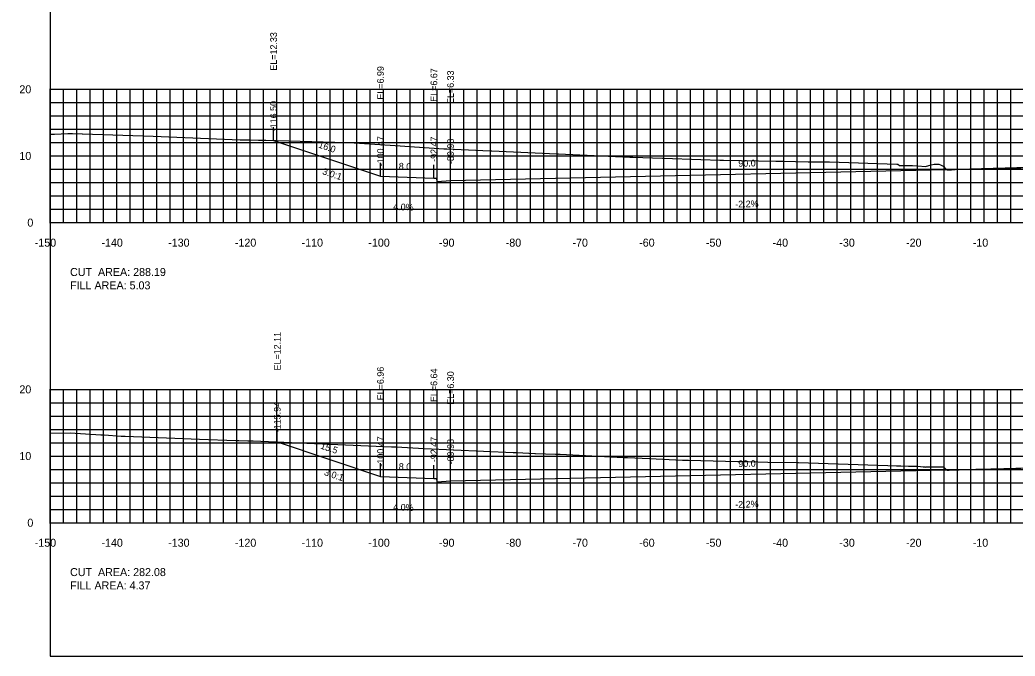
# Model space of a CAD drawing. Extents: x 1797419 to 1809236, y 248759 to 251512.
# Drawn here: x 1805196.5 to 1805345.6, y 250854.9 to 250950.3 of the extents above; entities that cross this region are included whole.
import ezdxf

# ---------------------------------------------------------------- set-up
doc = ezdxf.new("R2010")
doc.units = 0
for name, color, linetype in [('10', 7, 'Continuous'), ('3', 7, 'Continuous'), ('31', 7, 'Continuous'), ('4', 7, 'Continuous'), ('60', 7, 'Continuous'), ('ANNO-TXT', 7, 'Continuous'), ('CL-CNST', 7, 'Continuous'), ('Level 62', 7, 'Continuous'), ('M-ROADS', 7, 'Continuous')]:
    doc.layers.add(name, color=color, linetype=linetype)

msp = doc.modelspace()

# ---------------------------------------------------------------- linework, layer by layer
for p, q in [((1805234.5, 250932.22), (1805234.5, 250934.22)), ((1805250.53, 250926.88), (1805250.53, 250928.88)), ((1805258.53, 250926.56), (1805258.53, 250928.56)), ((1805261.03, 250926.22), (1805261.03, 250928.22)), ((1805235.06, 250887), (1805235.06, 250889)), ((1805250.53, 250881.84), (1805250.53, 250883.84)), ((1805258.53, 250881.52), (1805258.53, 250883.52)), ((1805261.03, 250881.19), (1805261.03, 250883.19))]:
    msp.add_line(p, q)
msp.add_lwpolyline([(1805201, 250854.89), (1805501, 250854.89), (1805501, 251044.89), (1805201, 251044.89)], close=True)
at = {"layer": '60'}
for p, q in [((1805200.94, 250939.89), (1805201, 250939.89)), ((1805201, 250919.89), (1805201, 250939.89)), ((1805200.94, 250929.89), (1805201, 250929.89)), ((1805200.94, 250919.89), (1805201, 250919.89)), ((1805201, 250919.89), (1805501, 250919.89)), ((1805201, 250919.83), (1805201, 250919.89)), ((1805211, 250919.83), (1805211, 250919.89)), ((1805221, 250919.83), (1805221, 250919.89)), ((1805231, 250919.83), (1805231, 250919.89)), ((1805241, 250919.83), (1805241, 250919.89)), ((1805251, 250919.83), (1805251, 250919.89)), ((1805261, 250919.83), (1805261, 250919.89)), ((1805271, 250919.83), (1805271, 250919.89)), ((1805281, 250919.83), (1805281, 250919.89)), ((1805291, 250919.83), (1805291, 250919.89)), ((1805301, 250919.83), (1805301, 250919.89)), ((1805311, 250919.83), (1805311, 250919.89)), ((1805321, 250919.83), (1805321, 250919.89)), ((1805331, 250919.83), (1805331, 250919.89)), ((1805341, 250919.83), (1805341, 250919.89)), ((1805200.94, 250894.89), (1805201, 250894.89)), ((1805201, 250874.89), (1805201, 250894.89)), ((1805200.94, 250884.89), (1805201, 250884.89)), ((1805200.94, 250874.89), (1805201, 250874.89)), ((1805201, 250874.89), (1805501, 250874.89)), ((1805201, 250874.83), (1805201, 250874.89)), ((1805211, 250874.83), (1805211, 250874.89)), ((1805221, 250874.83), (1805221, 250874.89)), ((1805231, 250874.83), (1805231, 250874.89)), ((1805241, 250874.83), (1805241, 250874.89)), ((1805251, 250874.83), (1805251, 250874.89)), ((1805261, 250874.83), (1805261, 250874.89)), ((1805271, 250874.83), (1805271, 250874.89)), ((1805281, 250874.83), (1805281, 250874.89)), ((1805291, 250874.83), (1805291, 250874.89)), ((1805301, 250874.83), (1805301, 250874.89)), ((1805311, 250874.83), (1805311, 250874.89)), ((1805321, 250874.83), (1805321, 250874.89)), ((1805331, 250874.83), (1805331, 250874.89)), ((1805341, 250874.83), (1805341, 250874.89))]:
    msp.add_line(p, q, dxfattribs=at)
at = {"layer": 'CL-CNST'}
for points in [[(1805234.5, 250932.22), (1805250.53, 250926.88), (1805258.53, 250926.56), (1805258.86, 250926.56), (1805259.03, 250926.06), (1805261.03, 250926.22), (1805351, 250928.2), (1805412.92, 250928.2), (1805414.92, 250928.04), (1805415.08, 250928.54), (1805415.41, 250928.54), (1805417.41, 250928.62), (1805422.41, 250928.72), (1805423.41, 250928.76), (1805425.93, 250927.92)], [(1805235.06, 250887), (1805250.53, 250881.84), (1805258.53, 250881.52), (1805258.86, 250881.52), (1805259.03, 250881.02), (1805261.03, 250881.19), (1805351, 250883.17), (1805414.66, 250882.89), (1805416.66, 250882.72), (1805416.82, 250883.22), (1805417.15, 250883.22), (1805419.15, 250883.3), (1805424.15, 250883.4), (1805425.15, 250883.44), (1805426.89, 250882.86)]]:
    msp.add_lwpolyline(points, dxfattribs=at)
at = {"layer": 'Level 62'}
for p, q in [((1805201, 250939.89), (1805501, 250939.89)), ((1805201, 250919.89), (1805201, 250939.89)), ((1805203, 250919.89), (1805203, 250939.89)), ((1805205, 250919.89), (1805205, 250939.89)), ((1805207, 250919.89), (1805207, 250939.89)), ((1805209, 250919.89), (1805209, 250939.89)), ((1805211, 250919.89), (1805211, 250939.89)), ((1805213, 250919.89), (1805213, 250939.89)), ((1805215, 250919.89), (1805215, 250939.89)), ((1805217, 250919.89), (1805217, 250939.89)), ((1805219, 250919.89), (1805219, 250939.89)), ((1805221, 250919.89), (1805221, 250939.89)), ((1805223, 250919.89), (1805223, 250939.89)), ((1805225, 250919.89), (1805225, 250939.89)), ((1805227, 250919.89), (1805227, 250939.89)), ((1805229, 250919.89), (1805229, 250939.89)), ((1805231, 250919.89), (1805231, 250939.89)), ((1805233, 250919.89), (1805233, 250939.89)), ((1805235, 250919.89), (1805235, 250939.89)), ((1805237, 250919.89), (1805237, 250939.89)), ((1805239, 250919.89), (1805239, 250939.89)), ((1805241, 250919.89), (1805241, 250939.89)), ((1805243, 250919.89), (1805243, 250939.89)), ((1805245, 250919.89), (1805245, 250939.89)), ((1805247, 250919.89), (1805247, 250939.89)), ((1805249, 250919.89), (1805249, 250939.89)), ((1805251, 250919.89), (1805251, 250939.89)), ((1805253, 250919.89), (1805253, 250939.89)), ((1805255, 250919.89), (1805255, 250939.89)), ((1805257, 250919.89), (1805257, 250939.89)), ((1805259, 250919.89), (1805259, 250939.89)), ((1805261, 250919.89), (1805261, 250939.89)), ((1805263, 250919.89), (1805263, 250939.89)), ((1805265, 250919.89), (1805265, 250939.89)), ((1805267, 250919.89), (1805267, 250939.89)), ((1805269, 250919.89), (1805269, 250939.89)), ((1805271, 250919.89), (1805271, 250939.89)), ((1805273, 250919.89), (1805273, 250939.89)), ((1805275, 250919.89), (1805275, 250939.89)), ((1805277, 250919.89), (1805277, 250939.89)), ((1805279, 250919.89), (1805279, 250939.89)), ((1805281, 250919.89), (1805281, 250939.89)), ((1805283, 250919.89), (1805283, 250939.89)), ((1805285, 250919.89), (1805285, 250939.89)), ((1805287, 250919.89), (1805287, 250939.89)), ((1805289, 250919.89), (1805289, 250939.89)), ((1805291, 250919.89), (1805291, 250939.89)), ((1805293, 250919.89), (1805293, 250939.89)), ((1805295, 250919.89), (1805295, 250939.89)), ((1805297, 250919.89), (1805297, 250939.89)), ((1805299, 250919.89), (1805299, 250939.89)), ((1805301, 250919.89), (1805301, 250939.89)), ((1805303, 250919.89), (1805303, 250939.89)), ((1805305, 250919.89), (1805305, 250939.89)), ((1805307, 250919.89), (1805307, 250939.89)), ((1805309, 250919.89), (1805309, 250939.89)), ((1805311, 250919.89), (1805311, 250939.89)), ((1805313, 250919.89), (1805313, 250939.89)), ((1805315, 250919.89), (1805315, 250939.89)), ((1805317, 250919.89), (1805317, 250939.89)), ((1805319, 250919.89), (1805319, 250939.89)), ((1805321, 250919.89), (1805321, 250939.89)), ((1805323, 250919.89), (1805323, 250939.89)), ((1805325, 250919.89), (1805325, 250939.89)), ((1805327, 250919.89), (1805327, 250939.89)), ((1805329, 250919.89), (1805329, 250939.89)), ((1805331, 250919.89), (1805331, 250939.89)), ((1805333, 250919.89), (1805333, 250939.89)), ((1805335, 250919.89), (1805335, 250939.89)), ((1805337, 250919.89), (1805337, 250939.89)), ((1805339, 250919.89), (1805339, 250939.89)), ((1805341, 250919.89), (1805341, 250939.89)), ((1805343, 250919.89), (1805343, 250939.89)), ((1805345, 250919.89), (1805345, 250939.89)), ((1805201, 250937.89), (1805501, 250937.89)), ((1805201, 250935.89), (1805501, 250935.89)), ((1805201, 250933.89), (1805501, 250933.89)), ((1805201, 250931.89), (1805501, 250931.89)), ((1805201, 250929.89), (1805501, 250929.89)), ((1805201, 250927.89), (1805501, 250927.89)), ((1805201, 250925.89), (1805501, 250925.89)), ((1805201, 250923.89), (1805501, 250923.89)), ((1805201, 250921.89), (1805501, 250921.89)), ((1805201, 250919.89), (1805501, 250919.89)), ((1805201, 250894.89), (1805501, 250894.89)), ((1805201, 250874.89), (1805201, 250894.89)), ((1805203, 250874.89), (1805203, 250894.89)), ((1805205, 250874.89), (1805205, 250894.89)), ((1805207, 250874.89), (1805207, 250894.89)), ((1805209, 250874.89), (1805209, 250894.89)), ((1805211, 250874.89), (1805211, 250894.89)), ((1805213, 250874.89), (1805213, 250894.89)), ((1805215, 250874.89), (1805215, 250894.89)), ((1805217, 250874.89), (1805217, 250894.89)), ((1805219, 250874.89), (1805219, 250894.89)), ((1805221, 250874.89), (1805221, 250894.89)), ((1805223, 250874.89), (1805223, 250894.89)), ((1805225, 250874.89), (1805225, 250894.89)), ((1805227, 250874.89), (1805227, 250894.89)), ((1805229, 250874.89), (1805229, 250894.89)), ((1805231, 250874.89), (1805231, 250894.89)), ((1805233, 250874.89), (1805233, 250894.89)), ((1805235, 250874.89), (1805235, 250894.89)), ((1805237, 250874.89), (1805237, 250894.89)), ((1805239, 250874.89), (1805239, 250894.89)), ((1805241, 250874.89), (1805241, 250894.89)), ((1805243, 250874.89), (1805243, 250894.89)), ((1805245, 250874.89), (1805245, 250894.89)), ((1805247, 250874.89), (1805247, 250894.89)), ((1805249, 250874.89), (1805249, 250894.89)), ((1805251, 250874.89), (1805251, 250894.89)), ((1805253, 250874.89), (1805253, 250894.89)), ((1805255, 250874.89), (1805255, 250894.89)), ((1805257, 250874.89), (1805257, 250894.89)), ((1805259, 250874.89), (1805259, 250894.89)), ((1805261, 250874.89), (1805261, 250894.89)), ((1805263, 250874.89), (1805263, 250894.89)), ((1805265, 250874.89), (1805265, 250894.89)), ((1805267, 250874.89), (1805267, 250894.89)), ((1805269, 250874.89), (1805269, 250894.89)), ((1805271, 250874.89), (1805271, 250894.89)), ((1805273, 250874.89), (1805273, 250894.89)), ((1805275, 250874.89), (1805275, 250894.89)), ((1805277, 250874.89), (1805277, 250894.89)), ((1805279, 250874.89), (1805279, 250894.89)), ((1805281, 250874.89), (1805281, 250894.89)), ((1805283, 250874.89), (1805283, 250894.89)), ((1805285, 250874.89), (1805285, 250894.89)), ((1805287, 250874.89), (1805287, 250894.89)), ((1805289, 250874.89), (1805289, 250894.89)), ((1805291, 250874.89), (1805291, 250894.89)), ((1805293, 250874.89), (1805293, 250894.89)), ((1805295, 250874.89), (1805295, 250894.89)), ((1805297, 250874.89), (1805297, 250894.89)), ((1805299, 250874.89), (1805299, 250894.89)), ((1805301, 250874.89), (1805301, 250894.89)), ((1805303, 250874.89), (1805303, 250894.89)), ((1805305, 250874.89), (1805305, 250894.89)), ((1805307, 250874.89), (1805307, 250894.89)), ((1805309, 250874.89), (1805309, 250894.89)), ((1805311, 250874.89), (1805311, 250894.89)), ((1805313, 250874.89), (1805313, 250894.89)), ((1805315, 250874.89), (1805315, 250894.89)), ((1805317, 250874.89), (1805317, 250894.89)), ((1805319, 250874.89), (1805319, 250894.89)), ((1805321, 250874.89), (1805321, 250894.89)), ((1805323, 250874.89), (1805323, 250894.89)), ((1805325, 250874.89), (1805325, 250894.89)), ((1805327, 250874.89), (1805327, 250894.89)), ((1805329, 250874.89), (1805329, 250894.89)), ((1805331, 250874.89), (1805331, 250894.89)), ((1805333, 250874.89), (1805333, 250894.89)), ((1805335, 250874.89), (1805335, 250894.89)), ((1805337, 250874.89), (1805337, 250894.89)), ((1805339, 250874.89), (1805339, 250894.89)), ((1805341, 250874.89), (1805341, 250894.89)), ((1805343, 250874.89), (1805343, 250894.89)), ((1805345, 250874.89), (1805345, 250894.89)), ((1805201, 250892.89), (1805501, 250892.89)), ((1805201, 250890.89), (1805501, 250890.89)), ((1805201, 250888.89), (1805501, 250888.89)), ((1805201, 250886.89), (1805501, 250886.89)), ((1805201, 250884.89), (1805501, 250884.89)), ((1805201, 250882.89), (1805501, 250882.89)), ((1805201, 250880.89), (1805501, 250880.89)), ((1805201, 250878.89), (1805501, 250878.89)), ((1805201, 250876.89), (1805501, 250876.89)), ((1805201, 250874.89), (1805501, 250874.89))]:
    msp.add_line(p, q, dxfattribs=at)
at = {"layer": 'M-ROADS'}
for points in [[(1805201, 250933.16), (1805201.69, 250933.18), (1805203.64, 250933.26), (1805203.67, 250933.26), (1805204.01, 250933.26), (1805204.04, 250933.26), (1805204.35, 250933.26), (1805205.81, 250933.2), (1805205.87, 250933.2), (1805216.45, 250932.87), (1805229.48, 250932.33), (1805230.03, 250932.32), (1805230.07, 250932.32), (1805230.96, 250932.29), (1805232.25, 250932.27), (1805233.17, 250932.25), (1805233.35, 250932.25), (1805245.4, 250931.91), (1805245.59, 250931.91), (1805245.83, 250931.9), (1805252.71, 250931.48), (1805260, 250930.98), (1805260.3, 250930.97), (1805260.45, 250930.97), (1805266.99, 250930.65), (1805267.2, 250930.64), (1805276.96, 250930.21), (1805277.21, 250930.21), (1805287.9, 250929.71), (1805288.37, 250929.7), (1805292.78, 250929.56), (1805292.9, 250929.56), (1805298.56, 250929.38), (1805301.39, 250929.28), (1805301.75, 250929.28), (1805301.93, 250929.28), (1805309.77, 250929.12), (1805310.23, 250929.11), (1805310.83, 250929.1), (1805314.62, 250929.01), (1805314.69, 250929.01), (1805317.18, 250929), (1805317.28, 250929), (1805317.82, 250929.01), (1805327.9, 250928.68), (1805327.91, 250928.68), (1805328.05, 250928.68), (1805328.32, 250928.44), (1805328.47, 250928.45), (1805328.97, 250928.45), (1805329.17, 250928.45), (1805329.32, 250928.45), (1805329.54, 250928.45), (1805329.67, 250928.45), (1805330.29, 250928.44), (1805331.07, 250928.42), (1805332.22, 250928.32), (1805333.06, 250928.57), (1805333.49, 250928.66), (1805333.51, 250928.66), (1805333.86, 250928.66), (1805333.88, 250928.66), (1805334.19, 250928.66), (1805334.2, 250928.66), (1805334.2, 250928.66), (1805334.48, 250928.55), (1805334.95, 250928.32), (1805335.08, 250928.15), (1805335.41, 250927.81), (1805336.1, 250927.83), (1805336.14, 250927.84), (1805336.18, 250927.85), (1805336.18, 250927.85), (1805336.22, 250927.85), (1805336.27, 250927.85), (1805336.3, 250927.85), (1805336.32, 250927.85), (1805336.37, 250927.85), (1805336.44, 250927.84), (1805336.45, 250927.84), (1805336.51, 250927.85), (1805336.58, 250927.87), (1805336.64, 250927.88), (1805336.67, 250927.88), (1805336.77, 250927.9), (1805336.88, 250927.92), (1805336.91, 250927.93), (1805337.02, 250927.92), (1805337.02, 250927.92), (1805337.13, 250927.93), (1805349.38, 250928.25)], [(1805201, 250888.3), (1805204.02, 250888.38), (1805208.63, 250888.06), (1805209.03, 250888.05), (1805209.13, 250888.05), (1805211.66, 250887.89), (1805211.77, 250887.89), (1805212.24, 250887.89), (1805223.42, 250887.43), (1805228.86, 250887.21), (1805229.27, 250887.21), (1805229.3, 250887.21), (1805230.64, 250887.17), (1805231.37, 250887.15), (1805231.46, 250887.15), (1805252.2, 250886.29), (1805252.66, 250886.28), (1805252.88, 250886.27), (1805257.06, 250886.03), (1805270.43, 250885.43), (1805270.96, 250885.42), (1805273.67, 250885.29), (1805273.74, 250885.29), (1805276.76, 250885.16), (1805277.19, 250885.15), (1805277.45, 250885.15), (1805286.96, 250884.67), (1805287.33, 250884.66), (1805287.56, 250884.66), (1805290.86, 250884.51), (1805295.79, 250884.28), (1805296.19, 250884.27), (1805296.68, 250884.26), (1805304.08, 250884.06), (1805304.35, 250884.06), (1805304.8, 250884.06), (1805305.3, 250884.05), (1805305.66, 250884.05), (1805308.59, 250883.99), (1805313.1, 250883.93), (1805313.17, 250883.93), (1805326.58, 250883.47), (1805327.88, 250883.44), (1805327.91, 250883.44), (1805328.29, 250883.41), (1805328.3, 250883.41), (1805328.51, 250883.4), (1805329.67, 250883.35), (1805329.69, 250883.35), (1805330.71, 250883.38), (1805330.72, 250883.38), (1805331.09, 250883.37), (1805331.88, 250883.26), (1805332.09, 250883.25), (1805332.21, 250883.24), (1805332.29, 250883.27), (1805332.34, 250883.28), (1805334.56, 250883.27), (1805334.79, 250883.27), (1805334.93, 250883.28), (1805335.19, 250882.96), (1805335.43, 250882.79), (1805335.5, 250882.79), (1805335.5, 250882.79), (1805335.51, 250882.79), (1805335.52, 250882.79), (1805335.54, 250882.79), (1805335.54, 250882.79), (1805335.57, 250882.79), (1805335.62, 250882.79), (1805335.69, 250882.79), (1805335.76, 250882.79), (1805336.81, 250882.8), (1805337.25, 250882.8), (1805338.54, 250882.85), (1805349.34, 250883.19)]]:
    msp.add_lwpolyline(points, dxfattribs=at)

# ---------------------------------------------------------------- texts
for p in [(1805241.73, 250927.18), (1805242, 250882.05)]:
    msp.add_text('3.0:1', height=1, rotation=341.5651).set_placement(p)
at = {"layer": '10'}
for s, p in [('-150', (1805198.7, 250916.29)), ('-140', (1805208.7, 250916.29)), ('-130', (1805218.7, 250916.29)), ('-120', (1805228.7, 250916.29)), ('-110', (1805238.7, 250916.29)), ('-100', (1805248.7, 250916.29)), ('-90', (1805259.3, 250916.29)), ('-80', (1805269.3, 250916.29)), ('-70', (1805279.3, 250916.29)), ('-60', (1805289.3, 250916.29)), ('-50', (1805299.3, 250916.29)), ('-40', (1805309.3, 250916.29)), ('-30', (1805319.3, 250916.29)), ('-20', (1805329.3, 250916.29)), ('-10', (1805339.3, 250916.29)), ('-150', (1805198.7, 250871.29)), ('-140', (1805208.7, 250871.29)), ('-130', (1805218.7, 250871.29)), ('-120', (1805228.7, 250871.29)), ('-110', (1805238.7, 250871.29)), ('-100', (1805248.7, 250871.29)), ('-90', (1805259.3, 250871.29)), ('-80', (1805269.3, 250871.29)), ('-70', (1805279.3, 250871.29)), ('-60', (1805289.3, 250871.29)), ('-50', (1805299.3, 250871.29)), ('-40', (1805309.3, 250871.29)), ('-30', (1805319.3, 250871.29)), ('-20', (1805329.3, 250871.29)), ('-10', (1805339.3, 250871.29))]:
    msp.add_text(s, height=1.2, dxfattribs=at).set_placement(p)
at = {"layer": '3'}
for s, p in [('EL=12.33', (1805235, 250942.69)), ('EL=6.99', (1805251.03, 250938.34)), ('EL=6.67', (1805259.03, 250938.02)), ('EL=6.33', (1805261.53, 250937.69)), ('-116.50', (1805235, 250933.6)), ('-100.47', (1805251.03, 250928.34)), ('-92.47', (1805259.03, 250929.01)), ('-89.98', (1805261.53, 250928.68)), ('EL=12.11', (1805235.56, 250897.73)), ('EL=6.96', (1805251.03, 250893.26)), ('EL=6.64', (1805259.03, 250892.99)), ('EL=6.30', (1805261.53, 250892.58)), ('-115.94', (1805235.56, 250888.47)), ('-100.47', (1805251.03, 250883.31)), ('-92.47', (1805259.03, 250883.98)), ('-89.98', (1805261.53, 250883.65))]:
    msp.add_text(s, height=1, rotation=90, dxfattribs=at).set_placement(p)
at = {"layer": '31'}
for s, p in [('20', (1805196.4, 250939.29)), ('10', (1805196.4, 250929.29)), ('0', (1805197.6, 250919.29)), ('20', (1805196.4, 250894.29)), ('10', (1805196.4, 250884.29)), ('0', (1805197.6, 250874.29))]:
    msp.add_text(s, height=1.2, dxfattribs=at).set_placement(p)
at = {"layer": '4'}
for s, rotation, p in [('16.0', 341.5651, (1805241.14, 250931.17)), ('8.0', 357.7094, (1805253.25, 250927.87)), ('90.0', 1.2603, (1805304.17, 250928.27)), ('4.0%', 357.7094, (1805252.42, 250921.8)), ('-2.2%', 1.2603, (1805303.71, 250922.16)), ('15.5', 341.5651, (1805241.45, 250886.03)), ('8.0', 357.7094, (1805253.25, 250882.84)), ('90.0', 1.2603, (1805304.17, 250883.24)), ('4.0%', 357.7094, (1805252.42, 250876.77)), ('-2.2%', 1.2603, (1805303.71, 250877.13))]:
    msp.add_text(s, height=1, rotation=rotation, dxfattribs=at).set_placement(p)
at = {"layer": '60'}
for p in [(1805201, 250919.89), (1805201, 250874.89)]:
    msp.add_text('-', height=0.0001, dxfattribs=at).set_placement(p)
at = {"layer": 'ANNO-TXT'}
for s, p in [('CUT  AREA: 288.19', (1805204, 250911.89)), ('FILL AREA: 5.03', (1805204, 250909.89)), ('CUT  AREA: 282.08', (1805204, 250866.89)), ('FILL AREA: 4.37', (1805204, 250864.89))]:
    msp.add_text(s, height=1.2, dxfattribs=at).set_placement(p)

doc.saveas('drawing.dxf')
